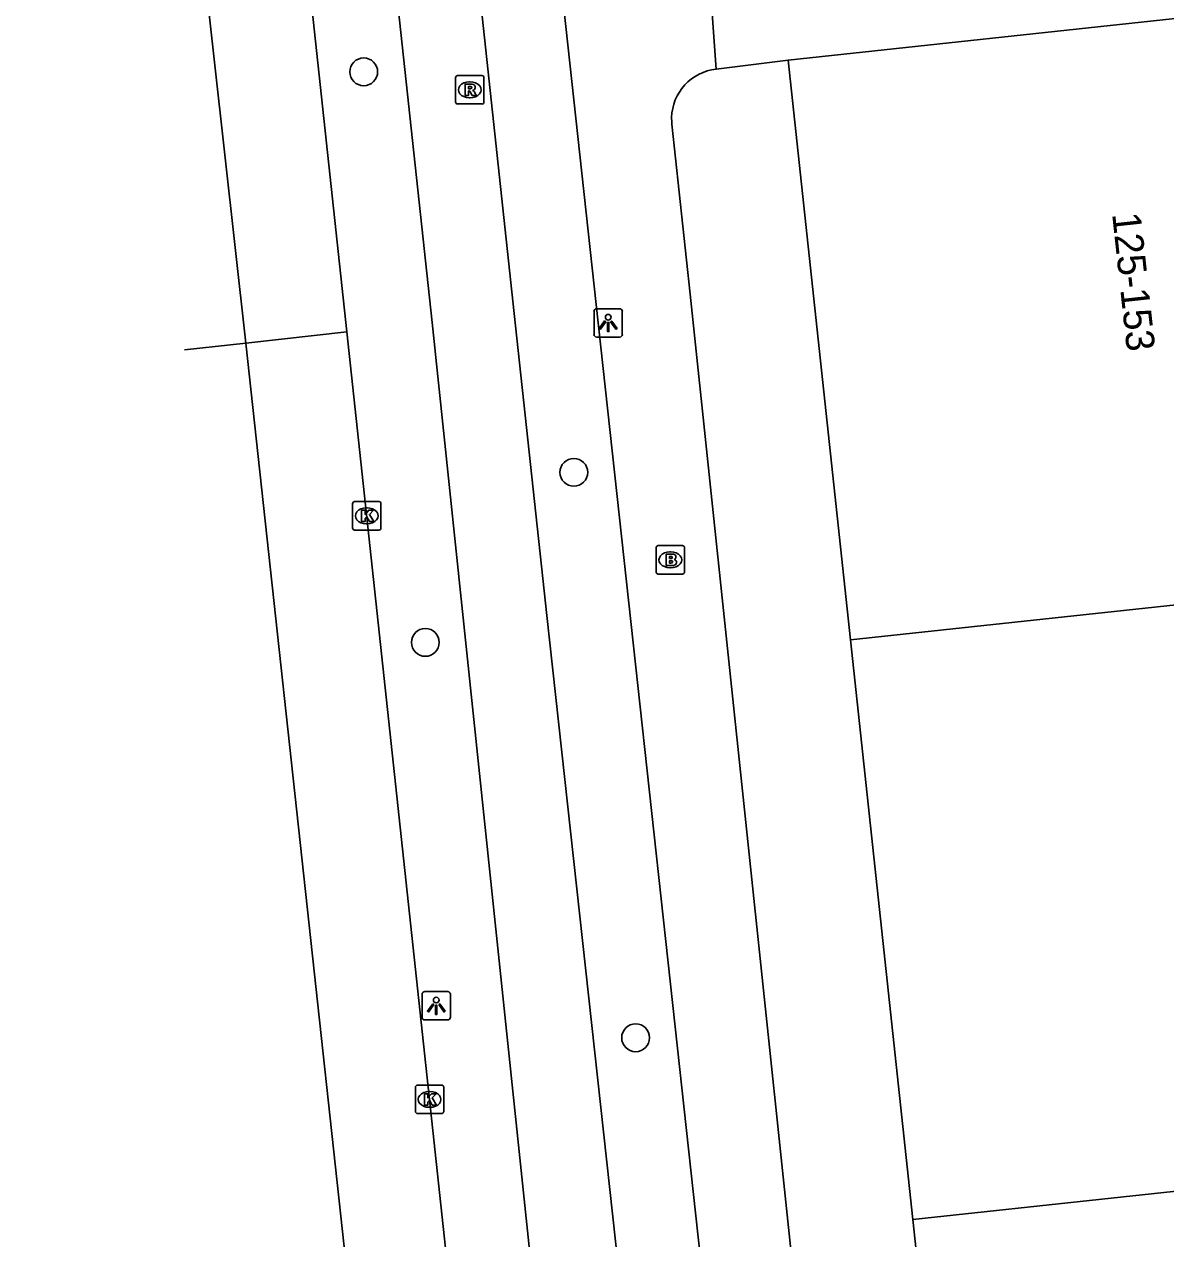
# Model space of a CAD drawing. Extents: x 161253 to 161848, y 384872 to 385383.
# Drawn here: x 161265.09 to 161305.25, y 385112.17 to 385154.91 of the extents above; entities that cross this region are included whole.
import ezdxf

# ---------------------------------------------------------------- set-up
doc = ezdxf.new("R2010")
doc.units = 0
for name, color, linetype in [('IMGEO_Boom', 7, 'Continuous'), ('IMGEO_Brandkraan', 7, 'Continuous'), ('IMGEO_Fietspad_gesloten', 7, 'Continuous'), ('IMGEO_Kolk', 7, 'Continuous'), ('IMGEO_Lichtpunt', 7, 'Continuous'), ('IMGEO_OVBaan_gesloten', 7, 'Continuous'), ('IMGEO_Pand', 7, 'Continuous'), ('IMGEO_Pand_nummerreeks', 7, 'Continuous'), ('IMGEO_Rioolput', 7, 'Continuous'), ('IMGEO_Voetpad_open', 7, 'Continuous')]:
    doc.layers.add(name, color=color, linetype=linetype)

msp = doc.modelspace()

# ---------------------------------------------------------------- linework, layer by layer
at = {"layer": 'IMGEO_Boom'}
for centre in [(161277.032, 385153.241), (161284.423, 385139.144), (161279.197, 385133.159), (161286.596, 385119.245)]:
    msp.add_circle(centre, 0.489, dxfattribs=at)
at = {"layer": 'IMGEO_Brandkraan'}
for p, q in [((161287.393, 385136.567), (161288.245, 385136.567)), ((161287.318, 385135.641), (161287.318, 385136.493)), ((161287.806, 385136.347), (161287.831, 385136.347)), ((161288.319, 385136.493), (161288.319, 385135.641)), ((161287.829, 385135.787), (161287.804, 385135.787)), ((161288.245, 385135.567), (161287.393, 385135.567))]:
    msp.add_line(p, q, dxfattribs=at)
for points in [[(161287.393, 385136.567), (161288.245, 385136.567)], [(161287.318, 385135.641), (161287.318, 385136.493)], [(161287.666, 385136.267), (161287.666, 385135.867), (161287.879, 385135.867)], [(161287.897, 385136.267), (161287.666, 385136.267)], [(161287.845, 385136.186), (161287.791, 385136.186), (161287.791, 385136.11)], [(161287.791, 385136.11), (161287.844, 385136.11)], [(161288.319, 385136.493), (161288.319, 385135.641)], [(161287.853, 385136.034), (161287.791, 385136.034), (161287.791, 385135.953)], [(161287.791, 385135.953), (161287.853, 385135.953)], [(161288.245, 385135.567), (161287.393, 385135.567)]]:
    msp.add_lwpolyline(points, dxfattribs=at)
for centre, radius, start, end in [((161287.395, 385136.491), 0.0765, 91.552, 178.448), ((161287.395, 385136.491), 0.0765, 91.552, 178.448), ((161288.243, 385136.491), 0.0765, 1.552, 88.448), ((161288.243, 385136.491), 0.0765, 1.552, 88.448), ((161287.846, 385136.148), 0.0379, 267.8285, 90.9355), ((161287.901, 385136.122), 0.145, 59.4692, 91.5367), ((161287.926, 385136.169), 0.0922, 285.5137, 58.1501), ((161287.854, 385135.993), 0.0404, 269.8759, 90.5077), ((161287.885, 385136.118), 0.251, 268.6676, 293.5347), ((161287.931, 385135.977), 0.105, 301.3115, 78.989), ((161287.395, 385135.643), 0.0765, 181.552, 268.448), ((161287.395, 385135.643), 0.0765, 181.552, 268.448), ((161288.243, 385135.643), 0.0765, 271.552, 358.448), ((161288.243, 385135.643), 0.0765, 271.552, 358.448)]:
    msp.add_arc(centre, radius, start, end, dxfattribs=at)
for centre, major_axis, ratio, start_param, end_param in [((161287.805, 385136.067), (-0.387, 0.002), 0.722429, 4.712389, 7.853982), ((161287.83, 385136.067), (-0.39, 0.002), 0.717154, 1.570796, 4.712389)]:
    msp.add_ellipse(centre, major_axis=major_axis, ratio=ratio, start_param=start_param, end_param=end_param, dxfattribs=at)
at = {"layer": 'IMGEO_Fietspad_gesloten'}
for points in [[(161304.405, 384916.554), (161304.284, 384917.771), (161304.157, 384919.005), (161298.845, 384967.161), (161292.634, 385023.456), (161286.649, 385075.675), (161279.435, 385144.415), (161273.278, 385201.438), (161272.519, 385207.639), (161271.091, 385227.08), (161270.412, 385243.981), (161269.728, 385255.799), (161268.918, 385265.585), (161266.954, 385291.9), (161266.061, 385304.636), (161265.987, 385305.638)], [(161294.971, 385029.929), (161289.778, 385076.19), (161287.158, 385100.538), (161283.468, 385134.103), (161282.325, 385144.732), (161275.66, 385206.665)]]:
    msp.add_lwpolyline(points, dxfattribs=at)
at = {"layer": 'IMGEO_Kolk'}
for p, q in [((161276.636, 385137.188), (161276.636, 385138.04)), ((161276.711, 385138.114), (161277.563, 385138.114)), ((161277.124, 385137.894), (161277.149, 385137.894)), ((161277.637, 385138.04), (161277.637, 385137.188)), ((161277.563, 385137.114), (161276.711, 385137.114)), ((161277.147, 385137.334), (161277.122, 385137.334)), ((161278.847, 385116.652), (161278.847, 385117.504)), ((161278.922, 385117.578), (161279.774, 385117.578)), ((161279.335, 385117.358), (161279.36, 385117.358)), ((161279.848, 385117.504), (161279.848, 385116.652)), ((161279.774, 385116.578), (161278.922, 385116.578)), ((161279.358, 385116.798), (161279.333, 385116.798))]:
    msp.add_line(p, q, dxfattribs=at)
for points in [[(161276.636, 385137.188), (161276.636, 385138.04)], [(161276.711, 385138.114), (161277.563, 385138.114)], [(161276.957, 385137.814), (161277.08, 385137.814), (161277.08, 385137.663), (161277.21, 385137.814), (161277.374, 385137.814), (161277.228, 385137.663), (161277.381, 385137.414), (161277.229, 385137.414), (161277.144, 385137.578), (161277.08, 385137.511), (161277.08, 385137.414), (161276.957, 385137.414), (161276.957, 385137.814)], [(161277.637, 385138.04), (161277.637, 385137.188)], [(161277.563, 385137.114), (161276.711, 385137.114)], [(161278.847, 385116.652), (161278.847, 385117.504)], [(161278.922, 385117.578), (161279.774, 385117.578)], [(161279.848, 385117.504), (161279.848, 385116.652)], [(161279.168, 385117.278), (161279.291, 385117.278), (161279.291, 385117.127), (161279.421, 385117.278), (161279.585, 385117.278), (161279.439, 385117.127), (161279.592, 385116.878), (161279.44, 385116.878), (161279.355, 385117.042), (161279.291, 385116.975), (161279.291, 385116.878), (161279.168, 385116.878), (161279.168, 385117.278)], [(161279.774, 385116.578), (161278.922, 385116.578)]]:
    msp.add_lwpolyline(points, dxfattribs=at)
for centre, start, end in [((161276.713, 385138.038), 91.552, 178.448), ((161276.713, 385138.038), 91.552, 178.448), ((161277.561, 385138.038), 1.552, 88.448), ((161277.561, 385138.038), 1.552, 88.448), ((161276.713, 385137.19), 181.552, 268.448), ((161276.713, 385137.19), 181.552, 268.448), ((161277.561, 385137.19), 271.552, 358.448), ((161277.561, 385137.19), 271.552, 358.448), ((161278.924, 385117.502), 91.552, 178.448), ((161278.924, 385117.502), 91.552, 178.448), ((161279.772, 385117.502), 1.552, 88.448), ((161279.772, 385117.502), 1.552, 88.448), ((161278.924, 385116.654), 181.552, 268.448), ((161278.924, 385116.654), 181.552, 268.448), ((161279.772, 385116.654), 271.552, 358.448), ((161279.772, 385116.654), 271.552, 358.448)]:
    msp.add_arc(centre, 0.0765, start, end, dxfattribs=at)
for centre, major_axis, ratio, start_param, end_param in [((161277.123, 385137.614), (-0.387, 0.002), 0.722429, 4.712389, 7.853982), ((161277.148, 385137.614), (-0.39, 0.002), 0.717154, 1.570796, 4.712389), ((161279.334, 385117.078), (-0.387, 0.002), 0.722429, 4.712389, 7.853982), ((161279.359, 385117.078), (-0.39, 0.002), 0.717154, 1.570796, 4.712389)]:
    msp.add_ellipse(centre, major_axis=major_axis, ratio=ratio, start_param=start_param, end_param=end_param, dxfattribs=at)
at = {"layer": 'IMGEO_Lichtpunt'}
for p, q in [((161285.133, 385144.808), (161285.133, 385144.001)), ((161285.133, 385144.808), (161285.133, 385144.001)), ((161286.035, 385144.903), (161285.227, 385144.903)), ((161286.035, 385144.903), (161285.227, 385144.903)), ((161286.129, 385144.001), (161286.129, 385144.808)), ((161286.129, 385144.001), (161286.129, 385144.808)), ((161285.227, 385143.907), (161286.035, 385143.907)), ((161285.227, 385143.907), (161286.035, 385143.907)), ((161279.084, 385120.775), (161279.084, 385119.968)), ((161279.084, 385120.775), (161279.084, 385119.968)), ((161279.986, 385120.87), (161279.178, 385120.87)), ((161279.986, 385120.87), (161279.178, 385120.87)), ((161280.08, 385119.968), (161280.08, 385120.775)), ((161280.08, 385119.968), (161280.08, 385120.775)), ((161279.178, 385119.874), (161279.986, 385119.874)), ((161279.178, 385119.874), (161279.986, 385119.874))]:
    msp.add_line(p, q, dxfattribs=at)
for points in [[(161285.507, 385144.472), (161285.546, 385144.444), (161285.358, 385144.182), (161285.32, 385144.209), (161285.507, 385144.472)], [(161285.609, 385144.424), (161285.656, 385144.424), (161285.656, 385144.102), (161285.609, 385144.102), (161285.609, 385144.424)], [(161285.719, 385144.444), (161285.757, 385144.471), (161285.944, 385144.209), (161285.905, 385144.181), (161285.719, 385144.444)], [(161279.458, 385120.439), (161279.497, 385120.411), (161279.309, 385120.149), (161279.271, 385120.176), (161279.458, 385120.439)], [(161279.56, 385120.391), (161279.607, 385120.391), (161279.607, 385120.069), (161279.56, 385120.069), (161279.56, 385120.391)], [(161279.67, 385120.411), (161279.708, 385120.438), (161279.895, 385120.176), (161279.856, 385120.148), (161279.67, 385120.411)]]:
    msp.add_lwpolyline(points, dxfattribs=at)
for centre in [(161285.632, 385144.606), (161279.583, 385120.573)]:
    msp.add_circle(centre, 0.0994, dxfattribs=at)
for centre, start, end in [((161285.227, 385144.808), 90, 180), ((161285.227, 385144.808), 90, 180), ((161286.035, 385144.808), 0, 90), ((161286.035, 385144.808), 0, 90), ((161285.227, 385144.001), 180, 270), ((161285.227, 385144.001), 180, 270), ((161286.035, 385144.001), 270, 0), ((161286.035, 385144.001), 270, 360), ((161279.178, 385120.775), 90, 180), ((161279.178, 385120.775), 90, 180), ((161279.986, 385120.775), 0, 90), ((161279.986, 385120.775), 0, 90), ((161279.178, 385119.968), 180, 270), ((161279.178, 385119.968), 180, 270), ((161279.986, 385119.968), 270, 0), ((161279.986, 385119.968), 270, 360)]:
    msp.add_arc(centre, 0.0946, start, end, dxfattribs=at)
at = {"layer": 'IMGEO_OVBaan_gesloten'}
for points in [[(161276.441, 385144.086), (161270.794, 385196.453), (161268.939, 385214.138)], [(161272.888, 385143.697), (161265.088, 385213.668)], [(161272.888, 385143.697), (161276.441, 385144.086)], [(161301.048, 384920.049), (161299.154, 384937.372), (161297.066, 384956.529), (161294.901, 384976.402), (161290.772, 385012.005), (161288.02, 385037.301), (161285.879, 385056.617), (161283.784, 385075.774), (161276.441, 385144.086)], [(161270.729, 385143.46), (161272.888, 385143.697)], [(161297.553, 384919.307), (161294.791, 384944.716), (161294.575, 384946.289), (161289.927, 384984.269), (161281.959, 385061.27), (161278.495, 385092.054), (161272.888, 385143.697)]]:
    msp.add_lwpolyline(points, dxfattribs=at)
at = {"layer": 'IMGEO_Pand'}
for points in [[(161291.96, 385153.649), (161305.913, 385155.151), (161306.352, 385151.066)], [(161294.156, 385133.247), (161291.96, 385153.649)], [(161308.121, 385134.749), (161294.156, 385133.247)], [(161296.352, 385112.845), (161294.156, 385133.247)], [(161310.306, 385114.346), (161296.352, 385112.845)], [(161298.549, 385092.443), (161296.352, 385112.845)]]:
    msp.add_lwpolyline(points, dxfattribs=at)
at = {"layer": 'IMGEO_Rioolput'}
for p, q in [((161280.26, 385152.183), (161280.26, 385153.035)), ((161280.335, 385153.109), (161281.187, 385153.109)), ((161280.748, 385152.889), (161280.773, 385152.889)), ((161281.261, 385153.035), (161281.261, 385152.183)), ((161280.771, 385152.329), (161280.746, 385152.329)), ((161281.187, 385152.109), (161280.335, 385152.109))]:
    msp.add_line(p, q, dxfattribs=at)
for points in [[(161280.26, 385152.183), (161280.26, 385153.035)], [(161280.335, 385153.109), (161281.187, 385153.109)], [(161280.849, 385152.807), (161280.597, 385152.809), (161280.597, 385152.409)], [(161281.261, 385153.035), (161281.261, 385152.183)], [(161280.597, 385152.409), (161280.721, 385152.409), (161280.721, 385152.571), (161280.732, 385152.571)], [(161280.775, 385152.728), (161280.721, 385152.728), (161280.721, 385152.647)], [(161280.721, 385152.647), (161280.773, 385152.647)], [(161280.779, 385152.542), (161280.85, 385152.409), (161280.99, 385152.409), (161280.925, 385152.535)], [(161281.187, 385152.109), (161280.335, 385152.109)]]:
    msp.add_lwpolyline(points, dxfattribs=at)
for centre, radius, start, end in [((161280.337, 385153.033), 0.0765, 91.552, 178.448), ((161280.337, 385153.033), 0.0765, 91.552, 178.448), ((161280.848, 385152.697), 0.109, 350.3612, 89.416), ((161281.185, 385153.033), 0.0765, 1.552, 88.448), ((161281.185, 385153.033), 0.0765, 1.552, 88.448), ((161280.731, 385152.518), 0.0533, 26.0293, 88.6989), ((161280.757, 385152.836), 0.19, 274.7715, 282.9687), ((161280.781, 385152.632), 0.0964, 77.0061, 93.1865), ((161280.795, 385152.689), 0.0378, 276.6634, 79.6772), ((161280.846, 385152.697), 0.112, 277.5842, 350.9817), ((161280.83, 385152.482), 0.108, 29.5134, 73.7905), ((161280.337, 385152.185), 0.0765, 181.552, 268.448), ((161280.337, 385152.185), 0.0765, 181.552, 268.448), ((161281.185, 385152.185), 0.0765, 271.552, 358.448), ((161281.185, 385152.185), 0.0765, 271.552, 358.448)]:
    msp.add_arc(centre, radius, start, end, dxfattribs=at)
for centre, major_axis, ratio, start_param, end_param in [((161280.747, 385152.609), (-0.387, 0.002), 0.722429, 4.712389, 7.853982), ((161280.772, 385152.609), (-0.39, 0.002), 0.717154, 1.570796, 4.712389)]:
    msp.add_ellipse(centre, major_axis=major_axis, ratio=ratio, start_param=start_param, end_param=end_param, dxfattribs=at)
at = {"layer": 'IMGEO_Voetpad_open'}
for points in [[(161275.697, 385233.018), (161279.427, 385198.062), (161285.204, 385145.048), (161292.7, 385076.509), (161292.829, 385075.469), (161292.978, 385075.471), (161297.713, 385030.826)], [(161289.281, 385155.459), (161289.426, 385153.334)], [(161289.426, 385153.334), (161291.96, 385153.649)], [(161299.044, 385045.595), (161295.732, 385076.938), (161288.519, 385145.411), (161287.873, 385151.4), (161287.866, 385151.482), (161287.864, 385151.639), (161287.875, 385151.796), (161287.901, 385151.951), (161287.94, 385152.103), (161287.993, 385152.251), (161288.058, 385152.393), (161288.137, 385152.53), (161288.227, 385152.658), (161288.328, 385152.779), (161288.439, 385152.889), (161288.56, 385152.989), (161288.69, 385153.078), (161288.827, 385153.156), (161288.97, 385153.22), (161289.118, 385153.272), (161289.271, 385153.31), (161289.426, 385153.334)]]:
    msp.add_lwpolyline(points, dxfattribs=at)

# ---------------------------------------------------------------- texts
at = {"layer": 'IMGEO_Pand_nummerreeks'}
msp.add_text('125-153', height=1, rotation=276.1763, dxfattribs=at).set_placement((161303.361, 385148.243))

doc.saveas('drawing.dxf')
